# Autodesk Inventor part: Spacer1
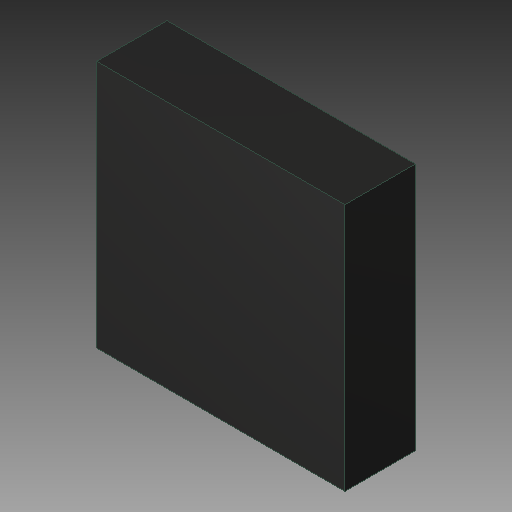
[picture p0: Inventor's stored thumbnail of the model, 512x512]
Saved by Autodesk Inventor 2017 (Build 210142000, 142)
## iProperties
Created: 2017-05
Part Number: Spacer1
Material: Generic
Document SubType Name: Modeling
Designer: Savy
Density: 1 g/cm^3
Appearance: Default
Author: Savy
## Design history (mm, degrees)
feature "SOLID1"
body "Solid1"
